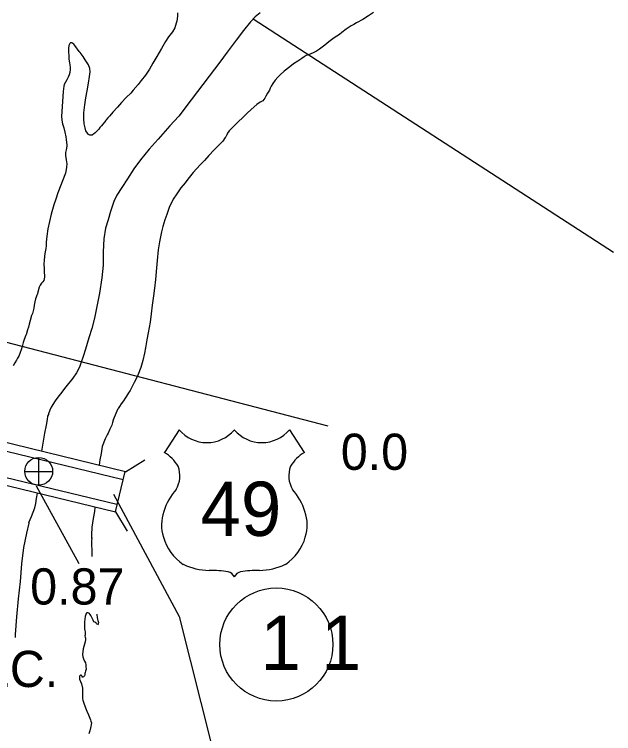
# Model space of a CAD drawing. Extents: x -939622 to -934222, y 1383701 to 1385301.
# Drawn here: x -935689.72 to -935668.73, y 1384029.55 to 1384054.73 of the extents above; entities that cross this region are included whole.
import ezdxf

# ---------------------------------------------------------------- set-up
doc = ezdxf.new("R2010")
doc.units = 0
for name, color, linetype in [('Level 15', 7, 'Continuous'), ('Level 2', 7, 'Continuous'), ('Level 20', 7, 'Continuous'), ('Level 22', 7, 'Continuous'), ('Level 25', 7, 'Continuous'), ('Level 26', 7, 'Continuous'), ('Level 27', 7, 'Continuous'), ('Level 3', 7, 'Continuous'), ('Level 9', 7, 'Continuous')]:
    doc.layers.add(name, color=color, linetype=linetype)

msp = doc.modelspace()

# ---------------------------------------------------------------- linework, layer by layer
at = {"layer": 'Level 15'}
for points in [[(-935695.297, 1384040.759), (-935695.202, 1384040.699), (-935695.124, 1384040.669), (-935694.915, 1384040.607), (-935694.776, 1384040.557), (-935694.355, 1384040.457), (-935690.823, 1384039.639), (-935685.911, 1384038.453)], [(-935695.771, 1384039.994), (-935695.608, 1384039.89), (-935695.412, 1384039.816), (-935695.195, 1384039.751), (-935695.031, 1384039.692), (-935694.561, 1384039.581), (-935691.03, 1384038.763), (-935686.126, 1384037.579)]]:
    msp.add_lwpolyline(points, dxfattribs=at)
at = {"layer": 'Level 2'}
msp.add_lwpolyline([(-935681.352, 1384054.573), (-935668.734, 1384046.408)], dxfattribs=at)
at = {"layer": 'Level 20'}
for p, q in [((-935685.826, 1384038.721), (-935691.524, 1384040.108)), ((-935685.826, 1384038.721), (-935685.15, 1384039.132)), ((-935691.878, 1384038.701), (-935686.18, 1384037.313)), ((-935686.182, 1384037.314), (-935685.839, 1384038.724)), ((-935686.18, 1384037.313), (-935685.769, 1384036.637))]:
    msp.add_line(p, q, dxfattribs=at)
at = {"layer": 'Level 22'}
for p, q in [((-935683.945, 1384040.19), (-935684.465, 1384039.387)), ((-935680.085, 1384040.19), (-935679.565, 1384039.387))]:
    msp.add_line(p, q, dxfattribs=at)
for centre, radius, start, end in [((-935682.978, 1384041.004), 1.264, 220.075, 319.6701), ((-935681.052, 1384041.004), 1.264, 220.3299, 319.925), ((-935685.143, 1384038.221), 1.349, 30.7809, 59.9883), ((-935678.887, 1384038.221), 1.349, 120.0117, 149.2191), ((-935684.846, 1384038.577), 0.925, 328.8105, 21.2108), ((-935679.184, 1384038.577), 0.925, 158.7892, 211.1895), ((-935682.428, 1384036.681), 2.157, 138.9565, 162.6913), ((-935681.602, 1384036.681), 2.157, 17.3087, 41.0435), ((-935683.14, 1384036.858), 1.426, 160.9576, 197.3819), ((-935680.89, 1384036.858), 1.426, 342.6181, 19.0424), ((-935682.908, 1384036.862), 1.65, 195.1074, 237.1312), ((-935681.122, 1384036.862), 1.65, 302.8688, 344.8926), ((-935682.877, 1384037.382), 2.118, 244.0771, 269.5779), ((-935682.828, 1384031.384), 3.88, 81.1942, 90.9539), ((-935681.202, 1384031.384), 3.88, 89.0461, 98.8058), ((-935681.153, 1384037.382), 2.118, 270.4221, 295.9229), ((-935682.343, 1384034.863), 0.372, 28.0342, 72.9864), ((-935681.687, 1384034.863), 0.372, 107.0136, 151.9658)]:
    msp.add_arc(centre, radius, start, end, dxfattribs=at)
at = {"layer": 'Level 25'}
for p, q in [((-935691.737, 1384043.709), (-935678.736, 1384040.325)), ((-935688.951, 1384038.228), (-935687.464, 1384035.503))]:
    msp.add_line(p, q, dxfattribs=at)
msp.add_lwpolyline([(-935686.242, 1384037.936), (-935683.946, 1384033.645), (-935682.798, 1384029.112)], dxfattribs=at)
at = {"layer": 'Level 26'}
for p, q in [((-935688.865, 1384038.245), (-935688.865, 1384039.22)), ((-935689.352, 1384038.732), (-935688.377, 1384038.732))]:
    msp.add_line(p, q, dxfattribs=at)
msp.add_circle((-935688.865, 1384038.732), 0.487, dxfattribs=at)
at = {"layer": 'Level 27'}
msp.add_circle((-935680.544, 1384032.67), 1.98, dxfattribs=at)
at = {"layer": 'Level 3'}
for points in [[(-935681.108, 1384054.793), (-935681.284, 1384054.643), (-935681.453, 1384054.47), (-935681.7, 1384054.169), (-935681.955, 1384053.832), (-935682.271, 1384053.405), (-935682.52, 1384053.065), (-935682.899, 1384052.575), (-935683.527, 1384051.736), (-935683.96, 1384051.171), (-935684.274, 1384050.828), (-935684.679, 1384050.369), (-935684.993, 1384050.015), (-935685.303, 1384049.645), (-935685.534, 1384049.324), (-935685.758, 1384048.976), (-935685.954, 1384048.669), (-935686.125, 1384048.408), (-935686.232, 1384048.183), (-935686.354, 1384047.837), (-935686.43, 1384047.536), (-935686.528, 1384047.248), (-935686.583, 1384046.869), (-935686.607, 1384046.416), (-935686.613, 1384045.958), (-935686.65, 1384045.51), (-935686.736, 1384044.97), (-935686.915, 1384044.095), (-935687.006, 1384043.735), (-935687.108, 1384043.411), (-935687.231, 1384043.011), (-935687.313, 1384042.76), (-935687.391, 1384042.518), (-935687.439, 1384042.384), (-935687.544, 1384042.183), (-935687.667, 1384041.994), (-935687.96, 1384041.631), (-935688.09, 1384041.456), (-935688.158, 1384041.378), (-935688.294, 1384041.197), (-935688.431, 1384040.983)], [(-935688.431, 1384040.983), (-935688.471, 1384040.872), (-935688.519, 1384040.75), (-935688.527, 1384040.728), (-935688.552, 1384040.664)], [(-935688.574, 1384040.549), (-935688.608, 1384040.348), (-935688.657, 1384040.075), (-935688.719, 1384039.722), (-935688.762, 1384039.438)], [(-935688.552, 1384040.664), (-935688.574, 1384040.549)], [(-935689.212, 1384036.94), (-935689.122, 1384037.153), (-935688.998, 1384037.456), (-935688.967, 1384037.605), (-935688.948, 1384037.778), (-935688.911, 1384037.964)], [(-935689.212, 1384036.94), (-935689.214, 1384036.922), (-935689.29, 1384036.573), (-935689.393, 1384036.065), (-935689.466, 1384035.493), (-935689.513, 1384034.87), (-935689.582, 1384034.27), (-935689.646, 1384033.635), (-935689.688, 1384033.018), (-935689.692, 1384032.911)]]:
    msp.add_lwpolyline(points, dxfattribs=at)
at = {"layer": 'Level 9'}
for points in [[(-935684.003, 1384054.783), (-935684.007, 1384054.675), (-935684.028, 1384054.493), (-935684.049, 1384054.426), (-935684.102, 1384054.264), (-935684.176, 1384054.125), (-935684.315, 1384053.947), (-935684.425, 1384053.782), (-935684.561, 1384053.538), (-935684.731, 1384053.259), (-935684.87, 1384053.023), (-935684.986, 1384052.813), (-935685.13, 1384052.602), (-935685.272, 1384052.424), (-935685.385, 1384052.277), (-935685.556, 1384052.082), (-935685.641, 1384051.979), (-935685.805, 1384051.824), (-935685.971, 1384051.647), (-935686.105, 1384051.485), (-935686.27, 1384051.305), (-935686.319, 1384051.249), (-935686.39, 1384051.17), (-935686.439, 1384051.114), (-935686.498, 1384051.045), (-935686.512, 1384051.02), (-935686.564, 1384050.964), (-935686.617, 1384050.889), (-935686.666, 1384050.832), (-935686.72, 1384050.77), (-935686.759, 1384050.717), (-935686.817, 1384050.657), (-935686.888, 1384050.581), (-935686.949, 1384050.539), (-935686.978, 1384050.517), (-935686.999, 1384050.507), (-935687.038, 1384050.505), (-935687.071, 1384050.506), (-935687.101, 1384050.52), (-935687.117, 1384050.531), (-935687.152, 1384050.569), (-935687.212, 1384050.651), (-935687.244, 1384050.761), (-935687.269, 1384050.898), (-935687.283, 1384051.075), (-935687.284, 1384051.292), (-935687.248, 1384051.562), (-935687.212, 1384051.816), (-935687.169, 1384052.056), (-935687.121, 1384052.324), (-935687.081, 1384052.554), (-935687.065, 1384052.727), (-935687.073, 1384052.835), (-935687.124, 1384052.971), (-935687.237, 1384053.144), (-935687.308, 1384053.255), (-935687.349, 1384053.31), (-935687.416, 1384053.397), (-935687.445, 1384053.432), (-935687.509, 1384053.517), (-935687.541, 1384053.557), (-935687.599, 1384053.645), (-935687.634, 1384053.686), (-935687.671, 1384053.72), (-935687.69, 1384053.737), (-935687.729, 1384053.742), (-935687.75, 1384053.735), (-935687.773, 1384053.718), (-935687.806, 1384053.645), (-935687.822, 1384053.538), (-935687.825, 1384053.478), (-935687.824, 1384053.394), (-935687.814, 1384053.307), (-935687.812, 1384053.253), (-935687.805, 1384053.16), (-935687.787, 1384053.034), (-935687.781, 1384052.971), (-935687.767, 1384052.869), (-935687.768, 1384052.812), (-935687.771, 1384052.7), (-935687.801, 1384052.615), (-935687.833, 1384052.538), (-935687.883, 1384052.442), (-935687.933, 1384052.356), (-935687.974, 1384052.278), (-935687.99, 1384052.22), (-935688.014, 1384052.039), (-935688.067, 1384051.163), (-935688.061, 1384051.033), (-935688.037, 1384050.905), (-935687.991, 1384050.759), (-935687.949, 1384050.611), (-935687.92, 1384050.449), (-935687.907, 1384050.354), (-935687.88, 1384050.159), (-935687.881, 1384050.114), (-935687.908, 1384049.989), (-935687.928, 1384049.892), (-935687.932, 1384049.783), (-935687.905, 1384049.655)], [(-935677.144, 1384054.797), (-935677.319, 1384054.678), (-935677.515, 1384054.557), (-935677.737, 1384054.433), (-935677.83, 1384054.377), (-935677.924, 1384054.328), (-935678.096, 1384054.211), (-935678.25, 1384054.099), (-935678.337, 1384054.034), (-935678.514, 1384053.918), (-935678.702, 1384053.768), (-935678.844, 1384053.653), (-935679.036, 1384053.511), (-935679.138, 1384053.446), (-935679.231, 1384053.394), (-935679.358, 1384053.34), (-935679.5, 1384053.291), (-935679.572, 1384053.243), (-935679.657, 1384053.185), (-935679.791, 1384053.1), (-935679.94, 1384053.003), (-935680.076, 1384052.9), (-935680.276, 1384052.74), (-935680.408, 1384052.62), (-935680.491, 1384052.535), (-935680.582, 1384052.431), (-935680.67, 1384052.319), (-935680.726, 1384052.226), (-935680.758, 1384052.146), (-935680.782, 1384052.082), (-935680.855, 1384051.973), (-935680.907, 1384051.865), (-935680.949, 1384051.8), (-935681.023, 1384051.703), (-935681.105, 1384051.657), (-935681.23, 1384051.576), (-935681.423, 1384051.408), (-935681.567, 1384051.271), (-935681.693, 1384051.145), (-935681.903, 1384050.946), (-935682.056, 1384050.8), (-935682.199, 1384050.652), (-935682.249, 1384050.574), (-935682.28, 1384050.513), (-935682.31, 1384050.448), (-935682.332, 1384050.417), (-935682.42, 1384050.298), (-935682.557, 1384050.16), (-935682.623, 1384050.09), (-935682.721, 1384049.989), (-935682.909, 1384049.788), (-935683.064, 1384049.621), (-935683.215, 1384049.461), (-935683.459, 1384049.202), (-935683.646, 1384048.968), (-935683.742, 1384048.84), (-935683.884, 1384048.662), (-935684.03, 1384048.45), (-935684.157, 1384048.267), (-935684.293, 1384047.974), (-935684.381, 1384047.723), (-935684.451, 1384047.542), (-935684.518, 1384047.304), (-935684.563, 1384047.115), (-935684.64, 1384046.769), (-935684.678, 1384046.49), (-935684.712, 1384046.115), (-935684.742, 1384045.86), (-935684.781, 1384045.455), (-935684.815, 1384045.143), (-935684.844, 1384044.879), (-935684.889, 1384044.552), (-935684.93, 1384044.252), (-935684.961, 1384043.952), (-935685.034, 1384043.582), (-935685.083, 1384043.332), (-935685.127, 1384043.056), (-935685.157, 1384042.871), (-935685.215, 1384042.615)], [(-935687.905, 1384049.655), (-935687.888, 1384049.556), (-935687.883, 1384049.514), (-935687.892, 1384049.372), (-935687.928, 1384049.169), (-935688.19, 1384048.488), (-935688.261, 1384048.265), (-935688.339, 1384048.06), (-935688.432, 1384047.736), (-935688.492, 1384047.483), (-935688.547, 1384047.228), (-935688.586, 1384046.97), (-935688.606, 1384046.761), (-935688.609, 1384046.631), (-935688.62, 1384046.531), (-935688.651, 1384046.358), (-935688.67, 1384046.135), (-935688.681, 1384045.977), (-935688.678, 1384045.845), (-935688.67, 1384045.668), (-935688.668, 1384045.614), (-935688.667, 1384045.532), (-935688.686, 1384045.417), (-935688.719, 1384045.364), (-935688.765, 1384045.326), (-935688.816, 1384045.251), (-935688.855, 1384045.177), (-935688.918, 1384044.918), (-935688.926, 1384044.897), (-935688.956, 1384044.835), (-935688.98, 1384044.771), (-935689.005, 1384044.673), (-935689.024, 1384044.555), (-935689.04, 1384044.452), (-935689.06, 1384044.351), (-935689.085, 1384044.257), (-935689.112, 1384044.186), (-935689.167, 1384044.009), (-935689.198, 1384043.89), (-935689.226, 1384043.781), (-935689.257, 1384043.689), (-935689.309, 1384043.515), (-935689.318, 1384043.499), (-935689.377, 1384043.349), (-935689.414, 1384043.242), (-935689.45, 1384043.105), (-935689.48, 1384042.989), (-935689.512, 1384042.891), (-935689.563, 1384042.768), (-935689.608, 1384042.691), (-935689.647, 1384042.626), (-935689.705, 1384042.53), (-935689.764, 1384042.43)], [(-935685.215, 1384042.615), (-935685.285, 1384042.374), (-935685.398, 1384042.101), (-935685.455, 1384041.969), (-935685.518, 1384041.842), (-935685.604, 1384041.679), (-935685.665, 1384041.564), (-935685.684, 1384041.527), (-935685.721, 1384041.478), (-935685.788, 1384041.369), (-935685.841, 1384041.291), (-935685.897, 1384041.204), (-935685.973, 1384041.095), (-935686.038, 1384041.005), (-935686.088, 1384040.933)], [(-935686.244, 1384040.552), (-935686.088, 1384040.933)], [(-935686.244, 1384040.552), (-935686.256, 1384040.523), (-935686.28, 1384040.447), (-935686.309, 1384040.353), (-935686.373, 1384040.208), (-935686.433, 1384040.073), (-935686.464, 1384040.011)], [(-935686.464, 1384040.011), (-935686.534, 1384039.877), (-935686.645, 1384039.599), (-935686.682, 1384039.357), (-935686.725, 1384039.134), (-935686.75, 1384038.948)], [(-935687.008, 1384036.385), (-935687.01, 1384036.509), (-935686.992, 1384036.781), (-935686.942, 1384037.079), (-935686.905, 1384037.332), (-935686.893, 1384037.469)], [(-935687.005, 1384036.4), (-935687.008, 1384036.385), (-935687.014, 1384036.312), (-935687.009, 1384035.818), (-935687, 1384035.751)], [(-935686.83, 1384033.727), (-935686.829, 1384033.713), (-935686.816, 1384033.62), (-935686.804, 1384033.551), (-935686.794, 1384033.509), (-935686.783, 1384033.474), (-935686.776, 1384033.435), (-935686.783, 1384033.398), (-935686.809, 1384033.364), (-935686.822, 1384033.379), (-935686.838, 1384033.405), (-935686.853, 1384033.423), (-935686.869, 1384033.434), (-935686.899, 1384033.448), (-935686.93, 1384033.462), (-935686.943, 1384033.485), (-935686.959, 1384033.518), (-935686.985, 1384033.571), (-935687.015, 1384033.633), (-935687.044, 1384033.683), (-935687.06, 1384033.725), (-935687.095, 1384033.768), (-935687.144, 1384033.784), (-935687.165, 1384033.781), (-935687.183, 1384033.777), (-935687.203, 1384033.758), (-935687.241, 1384033.651), (-935687.263, 1384033.469), (-935687.26, 1384033.325), (-935687.259, 1384033.222), (-935687.251, 1384033.159), (-935687.237, 1384033.118), (-935687.235, 1384033.063), (-935687.242, 1384033.012), (-935687.246, 1384032.973), (-935687.238, 1384032.925), (-935687.228, 1384032.886), (-935687.229, 1384032.841), (-935687.244, 1384032.762), (-935687.309, 1384032.512), (-935687.334, 1384032.321), (-935687.316, 1384032.234), (-935687.292, 1384032.163), (-935687.259, 1384032.086), (-935687.229, 1384032.027), (-935687.215, 1384031.958), (-935687.212, 1384031.901), (-935687.208, 1384031.805), (-935687.216, 1384031.774), (-935687.232, 1384031.731), (-935687.243, 1384031.692), (-935687.247, 1384031.652), (-935687.246, 1384031.616), (-935687.262, 1384031.573), (-935687.273, 1384031.555), (-935687.288, 1384031.542), (-935687.3, 1384031.536), (-935687.317, 1384031.526), (-935687.332, 1384031.522), (-935687.338, 1384031.531), (-935687.345, 1384031.546), (-935687.361, 1384031.575)], [(-935687.361, 1384031.575), (-935687.374, 1384031.59), (-935687.398, 1384031.592), (-935687.413, 1384031.582), (-935687.436, 1384031.56), (-935687.432, 1384031.458), (-935687.401, 1384031.378), (-935687.365, 1384031.298), (-935687.335, 1384031.137), (-935687.332, 1384030.998), (-935687.331, 1384030.905), (-935687.335, 1384030.769), (-935687.324, 1384030.718), (-935687.3, 1384030.65), (-935687.223, 1384030.448), (-935687.179, 1384030.332), (-935687.126, 1384030.208), (-935687.097, 1384030.146), (-935687.056, 1384030.033), (-935687.036, 1384029.988), (-935687.022, 1384029.926), (-935687.023, 1384029.868), (-935687.035, 1384029.795), (-935687.077, 1384029.649), (-935687.105, 1384029.536)]]:
    msp.add_lwpolyline(points, dxfattribs=at)

# ---------------------------------------------------------------- texts
at = {"layer": 'Level 22'}
msp.add_text('49', height=1.9008, dxfattribs=at).set_placement((-935683.197, 1384036.471))
at = {"layer": 'Level 25'}
for s, p in [('0.0', (-935678.286, 1384038.785)), ('0.87', (-935689.163, 1384034.069)), ('END SEC.', (-935696.185, 1384031.181))]:
    msp.add_text(s, height=1.2672, dxfattribs=at).set_placement(p)
at = {"layer": 'Level 27'}
msp.add_text('1 1', height=1.9008, dxfattribs=at).set_placement((-935681.1, 1384031.78))

doc.saveas('drawing.dxf')
